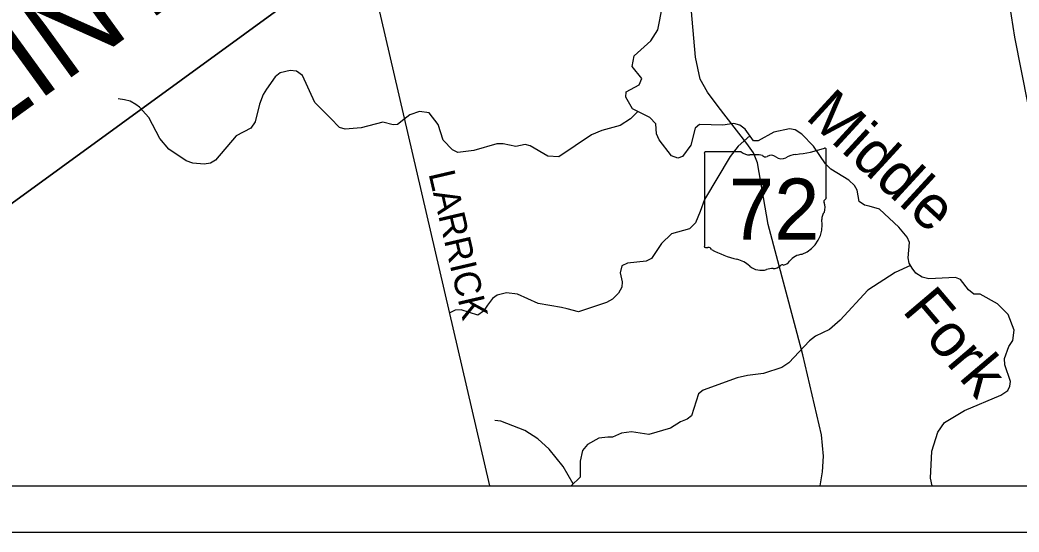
# Model space of a CAD drawing. Extents: x 0 to 34, y 0 to 22.
# Drawn here: x 4.871 to 7.032, y 14 to 15.108 of the extents above; entities that cross this region are included whole.
import ezdxf

# ---------------------------------------------------------------- set-up
doc = ezdxf.new("R2010")
doc.units = 0
for name, color, linetype in [('Default', 7, 'Continuous'), ('GM_X_County_Road', 7, 'Continuous'), ('GM_X_County_Road_Text', 7, 'Continuous'), ('GM_X_County_Text', 7, 'Continuous'), ('GM_X_Minor_River', 7, 'Continuous'), ('GM_X_Minor_River_Text', 7, 'Continuous'), ('GM_X_State_Location', 7, 'Continuous'), ('GM_X_State_Route', 7, 'Continuous'), ('GM_X_State_Shield', 7, 'Continuous'), ('GM_X_Township_Road', 7, 'Continuous'), ('SH_Cut_Line', 7, 'Continuous'), ('SH_Data', 7, 'Continuous')]:
    doc.layers.add(name, color=color, linetype=linetype)

msp = doc.modelspace()

# ---------------------------------------------------------------- linework, layer by layer
at = {"layer": 'Default'}
msp.add_lwpolyline([(6.6858, 19.0362), (6.6949, 19.1537), (6.8302, 20.9), (3.1229, 20.9), (2.9275, 20.8467), (2.2946, 20.6707), (2.1, 20.6202), (2.1, 17.1279), (2.1211, 17.1003), (3.2076, 15.5689), (3.4902, 15.1704), (4.0558, 14.3671), (4.1658, 14.2105), (4.302, 14.3105), (5.6165, 15.2674), (6.0871, 15.6176), (6.2834, 15.7529), (6.4392, 15.8657), (6.5428, 17.1931), (6.5451, 17.2211), (6.6309, 18.3364), (6.6363, 18.3979), (6.6654, 18.7733)], dxfattribs=at)
msp.add_lwpolyline([(4.022, 14.1), (8.9, 14.1), (8.9, 15.8067), (8.1324, 15.8252), (7.3679, 15.8435), (6.5786, 15.8624), (6.4392, 15.8657), (6.2834, 15.7529), (6.0871, 15.6176), (5.6165, 15.2674), (4.302, 14.3105), (4.1658, 14.2105)], close=True, dxfattribs=at)
at = {"layer": 'GM_X_County_Road'}
msp.add_line((5.8876, 14.1), (5.6167, 15.2669), dxfattribs=at)
at = {"layer": 'GM_X_Minor_River'}
for points in [[(7.0217, 14.4368), (7.0085, 14.4709), (6.9857, 14.4936), (6.9483, 14.5143), (6.9343, 14.5149), (6.923, 14.5242), (6.9055, 14.5461), (6.8949, 14.5509), (6.8374, 14.5476), (6.823, 14.5512), (6.8091, 14.5598), (6.8009, 14.5709), (6.7946, 14.582), (6.7925, 14.5935), (6.7956, 14.6261), (6.7901, 14.6376), (6.7726, 14.6595), (6.7306, 14.6985), (6.7079, 14.705), (6.698, 14.707), (6.6863, 14.7152), (6.6818, 14.7396), (6.6762, 14.7499), (6.6642, 14.7611), (6.625, 14.7849), (6.6138, 14.7965), (6.5878, 14.8345), (6.5623, 14.8607), (6.548, 14.87), (6.5355, 14.8725), (6.5015, 14.8651), (6.4677, 14.8466), (6.4575, 14.8467), (6.4396, 14.8713), (6.4279, 14.8806), (6.4151, 14.8842), (6.3914, 14.88), (6.3412, 14.8816), (6.3316, 14.8741), (6.3223, 14.8367), (6.304, 14.8126), (6.2941, 14.809), (6.2801, 14.8141), (6.2536, 14.8484), (6.2477, 14.8617), (6.2461, 14.8834), (6.2334, 14.8969), (6.1957, 14.9157), (6.1812, 14.9407), (6.1826, 14.9524), (6.2102, 14.9679), (6.2161, 14.9815), (6.1956, 15.0073), (6.1994, 15.03), (6.2356, 15.0625), (6.2505, 15.0866), (6.2612, 15.1381)], [(6.2073, 14.91), (6.1919, 14.8941), (6.1692, 14.8797), (6.1295, 14.8689), (6.1069, 14.8593), (6.0366, 14.8118), (6.0126, 14.8133), (5.9745, 14.8355), (5.9639, 14.8387), (5.9437, 14.8341), (5.9164, 14.8399), (5.9023, 14.8397), (5.8523, 14.8253), (5.8179, 14.8209), (5.8062, 14.8267), (5.786, 14.8479), (5.7755, 14.8819), (5.7561, 14.9069), (5.7353, 14.9099), (5.7139, 14.903), (5.7011, 14.8926), (5.6877, 14.8817), (5.6781, 14.8808), (5.6554, 14.8868), (5.6088, 14.8742), (5.5741, 14.8713), (5.562, 14.8753), (5.5422, 14.8954), (5.5088, 14.9293), (5.4816, 14.9879), (5.4692, 14.9968), (5.4555, 14.9985), (5.4334, 14.9932), (5.423, 14.985), (5.4043, 14.9583), (5.3969, 14.9463), (5.3886, 14.9255), (5.3796, 14.8876), (5.3699, 14.8741), (5.3384, 14.8571), (5.2935, 14.8042), (5.2831, 14.7983), (5.269, 14.7962), (5.2447, 14.7981), (5.2299, 14.8033), (5.193, 14.8282), (5.1732, 14.8517), (5.1496, 14.8972), (5.1291, 14.9192)], [(5.1291, 14.9192), (5.1211, 14.9253), (5.1087, 14.9319), (5.0965, 14.9351), (5.0828, 14.9371)], [(6.4499, 14.8571), (6.4246, 14.8347), (6.4075, 14.8125), (6.352, 14.7192), (6.3425, 14.6935), (6.3322, 14.6689), (6.3194, 14.6558), (6.2805, 14.6454), (6.2588, 14.6241), (6.2374, 14.5921), (6.2255, 14.5862), (6.1851, 14.5815), (6.1732, 14.5756), (6.1692, 14.5609), (6.1738, 14.5411), (6.1729, 14.5297), (6.1655, 14.5169), (6.1527, 14.5041), (6.14, 14.4964), (6.0792, 14.4764), (6.0546, 14.4829), (6.0425, 14.4861), (5.992, 14.4945), (5.9471, 14.5145), (5.9231, 14.5175), (5.9029, 14.5122), (5.8933, 14.5055), (5.8824, 14.4908), (5.8734, 14.478), (5.8615, 14.4691), (5.8252, 14.4807), (5.8122, 14.4797), (5.7992, 14.4735)], [(6.7977, 14.5765), (6.7642, 14.5616), (6.705, 14.5234), (6.645, 14.4586), (6.6223, 14.4384), (6.5916, 14.4241), (6.5789, 14.414), (6.534, 14.3657), (6.5194, 14.3556), (6.4796, 14.3433), (6.445, 14.3389), (6.4224, 14.3336), (6.3486, 14.307), (6.3386, 14.2988), (6.3238, 14.2515), (6.3141, 14.244), (6.2996, 14.2386), (6.2781, 14.2245), (6.2311, 14.2111), (6.1939, 14.2166), (6.1725, 14.2139), (6.1526, 14.2051), (6.1423, 14.2049), (6.1233, 14.2033), (6.0987, 14.1896), (6.0878, 14.1761), (6.0825, 14.1534), (6.0828, 14.1184), (6.0634, 14.1)], [(6.8446, 14.1), (6.8409, 14.1166), (6.8434, 14.1751), (6.8566, 14.2163), (6.8713, 14.237), (6.9144, 14.2629), (6.9932, 14.2959), (7.0079, 14.306), (7.0126, 14.3158), (7.0139, 14.3256), (7.0015, 14.3619), (7.001, 14.3752), (7.0105, 14.4013), (7.0187, 14.4141), (7.0217, 14.4368)], [(6.0677, 14.1041), (6.0462, 14.1414), (6.0156, 14.1795), (5.9912, 14.2019), (5.963, 14.2198), (5.9112, 14.2396), (5.8979, 14.2413)]]:
    msp.add_lwpolyline(points, dxfattribs=at)
at = {"layer": 'GM_X_State_Route'}
msp.add_lwpolyline([(6.6018, 14.1), (6.6072, 14.1303), (6.6089, 14.1641), (6.605, 14.2102), (6.5646, 14.3834), (6.4897, 14.6653), (6.4666, 14.7987), (6.4578, 14.8201), (6.4436, 14.8409), (6.3816, 14.9206), (6.3581, 14.9518), (6.3425, 14.9801), (6.3326, 15.0275), (6.2826, 15.596), (6.2795, 15.671), (6.2837, 15.7524)], dxfattribs=at)
at = {"layer": 'GM_X_State_Shield'}
for p, q in [((6.3514, 14.8189), (6.3514, 14.6188)), ((6.4312, 14.8224), (6.354, 14.8224)), ((6.6151, 14.7226), (6.6151, 14.8273)), ((6.615, 14.7227), (6.6151, 14.7226))]:
    msp.add_line(p, q, dxfattribs=at)
for centre, radius, start, end in [((6.5211, 15.0952), 0.2796, 275.8445, 288.9065), ((6.6121, 14.8278), 0.00294, 351.8621, 97.738), ((6.3544, 14.8194), 0.00305, 98.1301, 188.1301), ((6.4496, 14.8456), 0.0296, 231.6195, 271.1119), ((6.4594, 14.71), 0.1064, 80.4867, 94.9883), ((6.4836, 14.8204), 0.00855, 219.7921, 297.1024), ((6.4961, 14.7973), 0.0178, 54.4667, 119.1411), ((6.519, 14.829), 0.0214, 233.8562, 294.8282), ((6.5568, 14.7612), 0.0563, 97.3462, 120.7689), ((6.6119, 14.7222), 0.00314, 289.6038, 7.7341), ((6.6144, 14.715), 0.00454, 107.944, 210.337), ((6.5855, 14.7017), 0.0273, 340.033, 23.6496), ((6.6256, 14.6788), 0.0198, 136.8065, 186.9296), ((6.5368, 14.6655), 0.0699, 292.3089, 8.9858), ((6.3544, 14.6184), 0.00308, 171.9584, 258.3066), ((6.3549, 14.6388), 0.0235, 267.339, 280.6039), ((6.3597, 14.6073), 0.00848, 29.7484, 93.2717), ((6.4668, 14.7871), 0.2019, 240.4129, 257.1985), ((6.5663, 14.5626), 0.0383, 94.4031, 142.5768), ((6.4066, 14.5289), 0.0632, 47.1842, 75.836), ((6.4749, 14.6063), 0.0401, 230.7004, 286.2918), ((6.4981, 14.5371), 0.0329, 85.6951, 111.2099), ((6.501, 14.5913), 0.0214, 268.777, 315.5493), ((6.5203, 14.5719), 0.00601, 65.7517, 132.6484), ((6.5178, 14.5994), 0.0226, 282.8732, 323.2771)]:
    msp.add_arc(centre, radius, start, end, dxfattribs=at)
at = {"layer": 'GM_X_Township_Road'}
msp.add_lwpolyline([(7.2512, 14.1), (7.1325, 14.605), (7.1181, 14.6116), (7.1099, 14.6333), (7.0235, 15.0709), (7.0125, 15.1398), (6.9982, 15.225), (6.8762, 15.3717), (6.6676, 15.6148), (6.5583, 15.7333), (6.5453, 15.7486)], dxfattribs=at)
at = {"layer": 'SH_Cut_Line'}
msp.add_lwpolyline([(6.6858, 19.0362), (6.6949, 19.1537), (6.8302, 20.9), (2.1, 20.9), (2.1, 14.1), (4.022, 14.1), (4.1658, 14.2105), (4.302, 14.3105), (5.6165, 15.2674), (6.0871, 15.6176), (6.2834, 15.7529), (6.4392, 15.8657), (6.5428, 17.1931), (6.5451, 17.2211), (6.6309, 18.3364), (6.6363, 18.3979), (6.6654, 18.7733)], dxfattribs=at)
at = {"layer": 'SH_Data'}
for p, q in [((2.1, 14.1), (8.9, 14.1)), ((2, 14), (9, 14))]:
    msp.add_line(p, q, dxfattribs=at)

# ---------------------------------------------------------------- texts
at = {"layer": 'GM_X_County_Road_Text'}
msp.add_text('LARRICK', height=0.05682, rotation=283.1241, dxfattribs=at).set_placement((5.7543, 14.7757))
at = {"layer": 'GM_X_County_Text'}
msp.add_text('CLINTON COUNTY', height=0.189394, rotation=35.9139, dxfattribs=at).set_placement((4.6459, 14.7404))
at = {"layer": 'GM_X_Minor_River_Text'}
for s, rotation, p in [('Middle', 317.404, (6.5679, 14.8956)), ('Fork', 310.2908, (6.7777, 14.4781))]:
    msp.add_text(s, height=0.09469, rotation=rotation, dxfattribs=at).set_placement(p)
at = {"layer": 'GM_X_State_Location'}
for s, p in [('s', (6.4803, 14.7056)), ('r', (6.4802, 14.7056))]:
    msp.add_text(s, height=0.000189, dxfattribs=at).set_placement(p)
msp.add_text('72', height=0.000189, rotation=0, dxfattribs=at).set_placement((6.4326, 14.6918))
at = {"layer": 'GM_X_State_Shield'}
msp.add_text('72', height=0.13184, dxfattribs=at).set_placement((6.4045, 14.6329))

doc.saveas('drawing.dxf')
